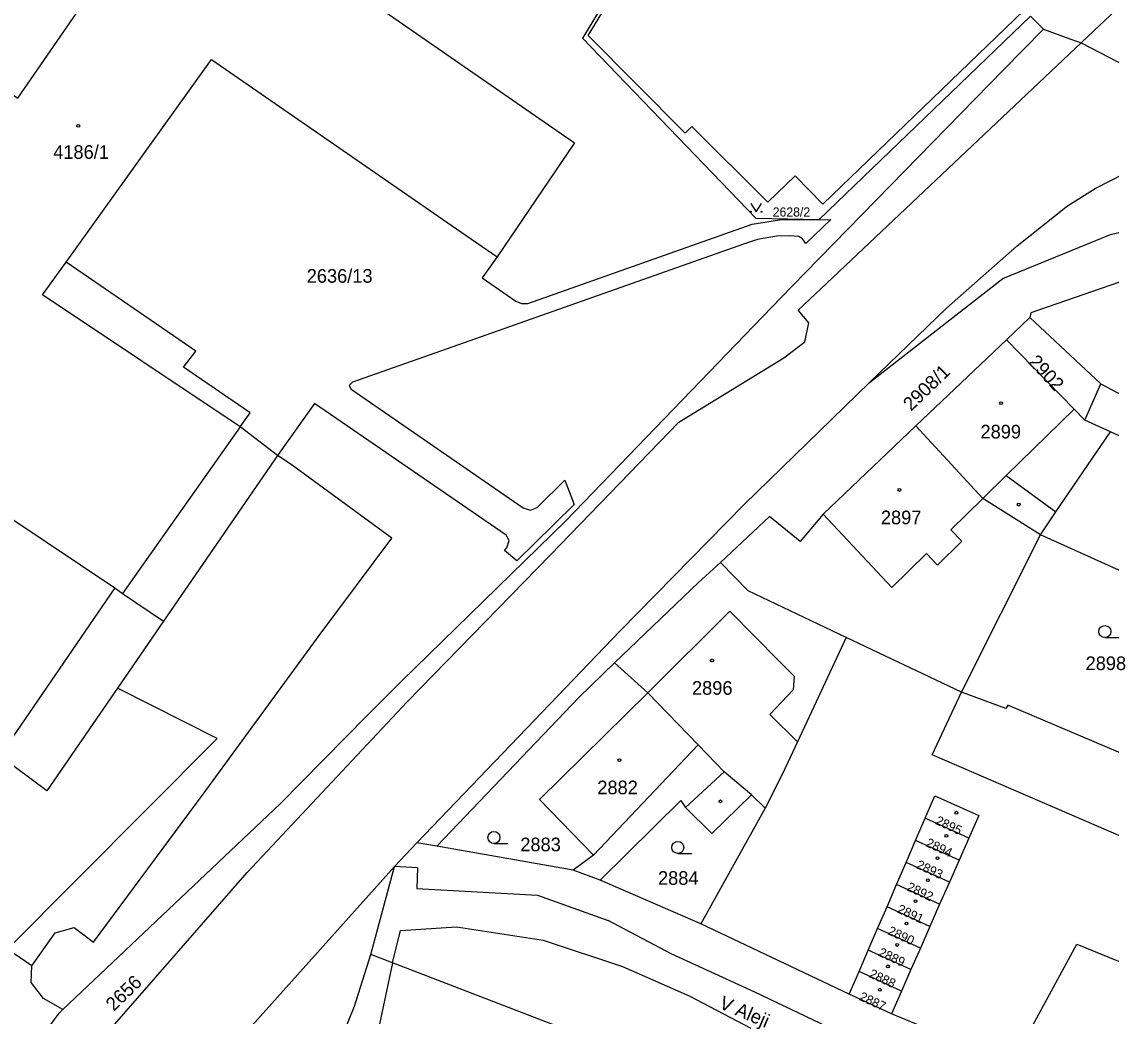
# Model space of a CAD drawing. Extents: x -527335 to -526256, y -1079142 to -1077809.
# Drawn here: x -527027.3 to -526891.4, y -1078723.7 to -1078599.7 of the extents above; entities that cross this region are included whole.
import ezdxf

# ---------------------------------------------------------------- set-up
doc = ezdxf.new("R2010")
doc.units = 0
for name, color, linetype in [('Vrstva 1', 7, 'Continuous'), ('Vrstva 2', 7, 'Continuous'), ('Vrstva 3', 7, 'Continuous'), ('Vrstva 4', 7, 'Continuous'), ('Vrstva 5', 7, 'Continuous'), ('Vrstva 7', 7, 'Continuous')]:
    doc.layers.add(name, color=color, linetype=linetype)

msp = doc.modelspace()

# ---------------------------------------------------------------- linework, layer by layer
at = {"layer": 'Vrstva 1'}
for p, q in [((-526895.17, -1078602.34), (-526879.54, -1078610.46)), ((-526901.58, -1078636.57), (-526904.48, -1078639.35)), ((-526892.72, -1078644.86), (-526901.58, -1078636.57)), ((-526904.48, -1078639.35), (-526915.77, -1078650.08)), ((-526894.69, -1078649.36), (-526892.72, -1078644.86)), ((-527000.1, -1078650.22), (-527014.76, -1078670.99)), ((-526891.48, -1078650.84), (-526894.69, -1078649.36)), ((-526910.1, -1078683.31), (-526900.22, -1078663.69)), ((-526884.81, -1078670.65), (-526900.22, -1078663.69)), ((-526910.1, -1078683.31), (-526924.49, -1078676.46)), ((-526949.23, -1078683.38), (-526953.38, -1078679.65)), ((-526934.57, -1078697.78), (-526936.31, -1078696.09)), ((-526934.57, -1078697.78), (-526942.6, -1078712.19)), ((-526915.81, -1078701.79), (-526914.61, -1078699.02)), ((-526909.18, -1078701.49), (-526914.61, -1078699.02)), ((-526916.99, -1078704.52), (-526915.81, -1078701.79)), ((-526910.4, -1078704.26), (-526915.81, -1078701.79)), ((-526909.18, -1078701.49), (-526910.4, -1078704.26)), ((-526978.03, -1078702.08), (-526980.85, -1078705.02)), ((-526975.57, -1078702.51), (-526978.03, -1078702.08)), ((-526958.56, -1078705.51), (-526975.57, -1078702.51)), ((-526918.19, -1078707.29), (-526916.99, -1078704.52)), ((-526911.6, -1078706.99), (-526916.99, -1078704.52)), ((-526910.4, -1078704.26), (-526911.6, -1078706.99)), ((-526980.85, -1078705.02), (-526998.63, -1078724.92)), ((-526955.16, -1078706.76), (-526958.56, -1078705.51)), ((-526942.6, -1078712.19), (-526955.16, -1078706.76)), ((-526919.38, -1078710.05), (-526918.19, -1078707.29)), ((-526912.82, -1078709.75), (-526918.19, -1078707.29)), ((-526911.6, -1078706.99), (-526912.82, -1078709.75)), ((-526920.56, -1078712.77), (-526919.38, -1078710.05)), ((-526914.03, -1078712.51), (-526919.38, -1078710.05)), ((-526912.82, -1078709.75), (-526914.03, -1078712.51)), ((-526924.11, -1078720.97), (-526942.6, -1078712.19)), ((-526921.72, -1078715.45), (-526920.56, -1078712.77)), ((-526915.22, -1078715.23), (-526920.56, -1078712.77)), ((-526914.03, -1078712.51), (-526915.22, -1078715.23)), ((-526922.88, -1078718.12), (-526921.72, -1078715.45)), ((-526916.4, -1078717.9), (-526921.72, -1078715.45)), ((-526915.22, -1078715.23), (-526916.4, -1078717.9)), ((-526924.11, -1078720.97), (-526922.88, -1078718.12)), ((-526917.58, -1078720.58), (-526922.88, -1078718.12)), ((-526916.4, -1078717.9), (-526917.58, -1078720.58)), ((-526918.83, -1078723.42), (-526924.11, -1078720.97)), ((-526917.58, -1078720.58), (-526918.83, -1078723.42))]:
    msp.add_line(p, q, dxfattribs=at)
for points in [[(-527032.9, -1078614.69), (-527028.96, -1078608.95), (-527028.74, -1078608.62), (-527027.84, -1078609.21), (-527013.93, -1078589.06), (-527018.97, -1078585.47), (-527022.71, -1078582.8), (-527034.32, -1078599.25), (-527035, -1078600.21), (-527045.31, -1078592.89), (-527044.64, -1078591.95), (-527045.34, -1078591.68), (-527030.72, -1078570.54), (-527019.5, -1078578.37), (-527020.66, -1078580.03), (-527011.71, -1078586.28), (-527007.77, -1078580.59), (-526958.39, -1078614.81), (-526968.02, -1078629.02)], [(-526886.71, -1078584.76), (-526887.47, -1078583.94), (-526927.4, -1078622.44), (-526930.86, -1078618.91), (-526934.27, -1078622.19), (-526943.73, -1078612.76), (-526944.56, -1078613.6), (-526956.67, -1078601.43), (-526954.52, -1078597.86), (-526954.82, -1078597.51)], [(-526895.17, -1078602.34), (-526893.54, -1078600.8), (-526885.48, -1078593.16)], [(-526954.82, -1078597.51), (-526957.37, -1078601.73), (-526935.75, -1078624.2), (-526927.86, -1078624.35), (-526901.5, -1078599), (-526901.11, -1078599.39)], [(-526901.11, -1078599.39), (-526900.32, -1078600.17), (-526899.88, -1078600.6)], [(-527022.2, -1078722.85), (-526995.09, -1078697.22), (-526984.19, -1078686.17), (-526979.99, -1078681.95), (-526959.44, -1078661.92), (-526932.63, -1078634.11), (-526929.59, -1078631.02), (-526904.86, -1078605.7), (-526899.88, -1078600.6)], [(-526899.88, -1078600.6), (-526897.02, -1078601.66), (-526895.17, -1078602.34)], [(-527072.22, -1078805.43), (-527063.35, -1078791.03), (-527051.39, -1078772.86), (-527021.8, -1078732.24), (-527016.31, -1078725.38), (-526999.22, -1078705.77), (-526979.26, -1078684.5), (-526961.36, -1078666.17), (-526945.34, -1078649.61), (-526932.24, -1078641.62), (-526929.63, -1078639.61), (-526929.14, -1078637.23), (-526930.46, -1078635.68), (-526927.65, -1078633), (-526895.17, -1078602.34)], [(-527000.1, -1078650.22), (-527024.76, -1078633.76), (-527021.82, -1078629.67), (-527003.67, -1078604.4), (-526973.08, -1078625.53), (-526968.02, -1078629.02)], [(-526921.59, -1078644.68), (-526911.97, -1078635.42), (-526903.16, -1078627.64), (-526896.85, -1078622.64), (-526893.43, -1078620.48), (-526889.76, -1078618.63), (-526885.07, -1078616.68), (-526879.09, -1078614.67), (-526871.32, -1078612.59), (-526869.37, -1078612.14)], [(-526921.59, -1078644.68), (-526904.95, -1078631.71), (-526891.51, -1078626.22), (-526880.24, -1078623.51), (-526871.73, -1078622.35), (-526857.21, -1078622.49), (-526853.17, -1078623.18)], [(-526968.02, -1078629.02), (-526969.91, -1078631.61), (-526965.71, -1078634.53), (-526965, -1078634.84), (-526964.22, -1078634.81), (-526936.22, -1078624.93), (-526932.79, -1078624.4), (-526926.41, -1078624.36), (-526929.51, -1078627.35), (-526929.91, -1078626.76), (-526930.39, -1078626.49), (-526931.57, -1078626.38), (-526933.16, -1078626.45), (-526935.56, -1078626.83), (-526937.3, -1078627.43), (-526974.99, -1078640.74), (-526986.08, -1078644.63), (-526986.49, -1078645.05), (-526986.23, -1078645.53), (-526964.78, -1078660.29), (-526963.85, -1078660.61), (-526963.02, -1078660.27), (-526959.57, -1078656.88), (-526958.42, -1078659.89), (-526960.97, -1078662.37), (-526965.58, -1078666.91), (-526967.12, -1078665.64), (-526966.8, -1078665.3), (-526966.51, -1078664.38), (-526966.91, -1078663.73), (-526990.82, -1078647.32), (-526995.44, -1078653.79), (-527000.1, -1078650.22)], [(-526878.81, -1078628.66), (-526882.67, -1078629.51), (-526901.46, -1078636.01), (-526901.58, -1078636.57)], [(-526894.69, -1078649.36), (-526896.02, -1078648), (-526904.48, -1078639.35)], [(-526978.03, -1078702.08), (-526952.67, -1078675.63), (-526937.2, -1078659.88), (-526921.59, -1078644.68)], [(-526892.72, -1078644.86), (-526888.78, -1078646.91), (-526881.81, -1078650.35)], [(-526915.77, -1078650.08), (-526927.35, -1078661.1), (-526930.24, -1078664.51), (-526934.06, -1078661.4), (-526940.18, -1078667.13)], [(-526900.22, -1078663.69), (-526907.42, -1078659.13), (-526915.77, -1078650.08)], [(-526900.22, -1078663.69), (-526898.33, -1078660.82), (-526891.48, -1078650.84)], [(-526884.81, -1078670.65), (-526875.97, -1078658.01), (-526891.48, -1078650.84)], [(-527028.7, -1078661.6), (-527015.73, -1078670.3), (-527014.76, -1078670.99)], [(-526940.18, -1078667.13), (-526942.9, -1078669.62), (-526953.38, -1078679.65)], [(-526924.49, -1078676.46), (-526936.71, -1078670.65), (-526940.18, -1078667.13)], [(-527014.76, -1078670.99), (-527009.64, -1078674.44), (-527015.39, -1078682.81)], [(-526924.49, -1078676.46), (-526930.54, -1078689.49), (-526931.74, -1078692.06), (-526932.57, -1078693.74), (-526934.57, -1078697.78)], [(-526953.38, -1078679.65), (-526957.82, -1078683.96), (-526975.57, -1078702.51)], [(-527015.39, -1078682.81), (-527024.2, -1078695.62), (-527030.14, -1078691.25), (-527037.08, -1078701.34), (-527042.08, -1078697.91)], [(-527022.2, -1078722.85), (-527024.62, -1078721.48), (-527026.17, -1078719.51), (-527026.1, -1078717.42), (-527029.13, -1078715.35), (-527002.95, -1078689.07), (-527015.39, -1078682.81)], [(-526949.23, -1078683.38), (-526962.73, -1078696.68), (-526956.02, -1078703.63), (-526958.56, -1078705.51)], [(-526936.31, -1078696.09), (-526939.72, -1078693.23), (-526942.93, -1078689.86), (-526949.23, -1078683.38)], [(-526887.47, -1078692.06), (-526904.29, -1078684.93), (-526904.54, -1078685.32), (-526910.1, -1078683.31)], [(-526955.16, -1078706.76), (-526945.11, -1078696.79), (-526944.54, -1078697.69), (-526941.25, -1078700.91), (-526936.31, -1078696.09)], [(-526914.61, -1078699.02), (-526913.4, -1078696.22), (-526907.94, -1078698.67), (-526909.18, -1078701.49)], [(-526943.47, -1078731.53), (-526981.07, -1078717.06), (-526983.77, -1078716), (-526980.85, -1078705.02)], [(-526903.84, -1078729.73), (-526895.72, -1078714.74), (-526874.21, -1078723.48)], [(-527026.84, -1078728.96), (-527025.8, -1078727.55), (-527022.69, -1078723.31), (-527022.2, -1078722.85)], [(-526903.84, -1078729.73), (-526908.52, -1078727.66), (-526909.18, -1078727.41), (-526918.83, -1078723.42)]]:
    msp.add_lwpolyline(points, dxfattribs=at)
at = {"layer": 'Vrstva 3'}
for p, q in [((-526892.21, -1078676.49), (-526890.46, -1078676.49)), ((-526968.43, -1078702.17), (-526966.68, -1078702.17)), ((-526945.49, -1078703.41), (-526943.74, -1078703.41))]:
    msp.add_line(p, q, dxfattribs=at)
msp.add_lwpolyline([(-526936.39, -1078622.38), (-526935.72, -1078623.39), (-526935.05, -1078622.38)], dxfattribs=at)
for centre, radius in [((-526936.39, -1078623.39), 0.067), ((-526935.05, -1078623.39), 0.067), ((-526892.21, -1078675.74), 0.75), ((-526968.43, -1078701.42), 0.75), ((-526945.49, -1078702.66), 0.75)]:
    msp.add_circle(centre, radius, dxfattribs=at)
at = {"layer": 'Vrstva 4'}
for p, q in [((-527005.61, -1078640.76), (-527021.82, -1078629.67)), ((-527007.15, -1078642.76), (-527005.61, -1078640.76)), ((-526998.84, -1078648.48), (-527007.15, -1078642.76)), ((-527000.1, -1078650.22), (-526998.84, -1078648.48)), ((-526904.5, -1078656.28), (-526896.02, -1078648)), ((-526995.44, -1078653.79), (-527009.64, -1078674.44)), ((-526993.74, -1078654.92), (-526995.44, -1078653.79)), ((-526981.15, -1078664.11), (-526993.74, -1078654.92)), ((-526907.42, -1078659.13), (-526904.5, -1078656.28)), ((-526904.5, -1078656.28), (-526898.33, -1078660.82)), ((-526911.43, -1078663.04), (-526907.42, -1078659.13)), ((-526927.35, -1078661.1), (-526918.8, -1078670.23)), ((-526910.03, -1078664.47), (-526911.43, -1078663.04)), ((-526990.1, -1078676.05), (-526981.15, -1078664.11)), ((-526913.07, -1078667.44), (-526910.03, -1078664.47)), ((-526918.8, -1078670.23), (-526914.47, -1078666)), ((-526914.47, -1078666), (-526913.07, -1078667.44)), ((-527015.73, -1078670.3), (-527030.14, -1078691.25)), ((-526949.23, -1078683.38), (-526939, -1078673.18)), ((-526939, -1078673.18), (-526932.89, -1078679.41)), ((-527004.71, -1078696.01), (-526990.1, -1078676.05)), ((-526932.89, -1078679.41), (-526930.97, -1078681.31)), ((-526930.97, -1078681.31), (-526931.09, -1078683.01)), ((-526931.09, -1078683.01), (-526934, -1078686.1)), ((-526913.74, -1078691.1), (-526910.1, -1078683.31)), ((-526934, -1078686.1), (-526930.54, -1078689.49)), ((-526956.02, -1078703.63), (-526942.93, -1078689.86)), ((-526884.03, -1078703.98), (-526913.74, -1078691.1)), ((-526944.54, -1078697.69), (-526939.72, -1078693.23)), ((-527018.38, -1078714.47), (-527004.71, -1078696.01)), ((-526977.98, -1078705.21), (-526980.85, -1078705.02)), ((-526977.98, -1078705.21), (-526978.05, -1078707.78)), ((-526978.05, -1078707.78), (-526962.99, -1078708.6)), ((-526962.99, -1078708.6), (-526954.18, -1078711.78)), ((-527023.18, -1078713.29), (-527020.8, -1078712.65)), ((-527020.8, -1078712.65), (-527018.38, -1078714.47)), ((-526980.09, -1078713), (-526973.08, -1078712.58)), ((-526973.08, -1078712.58), (-526962.3, -1078714.24)), ((-526946.33, -1078715.93), (-526954.18, -1078711.78)), ((-527026.1, -1078717.42), (-527023.18, -1078713.29)), ((-526981.07, -1078717.06), (-526980.09, -1078713)), ((-526962.3, -1078714.24), (-526952.38, -1078717.51)), ((-526985.84, -1078722.46), (-526983.77, -1078716)), ((-526935.89, -1078720.7), (-526946.33, -1078715.93)), ((-526981.07, -1078717.06), (-526982.85, -1078725.3)), ((-526952.38, -1078717.51), (-526944.09, -1078721.15)), ((-526925.87, -1078725.49), (-526935.89, -1078720.7)), ((-526944.09, -1078721.15), (-526936.39, -1078725.2)), ((-526987.91, -1078727.56), (-526985.84, -1078722.46))]:
    msp.add_line(p, q, dxfattribs=at)
at = {"layer": 'Vrstva 5'}
for centre in [(-527020.29, -1078612.68), (-526905.16, -1078647.26), (-526917.84, -1078658.08), (-526902.95, -1078659.91), (-526941.22, -1078679.35), (-526952.78, -1078691.78), (-526940.18, -1078696.91), (-526910.73, -1078698.33), (-526911.98, -1078701.22), (-526913.09, -1078703.99), (-526914.3, -1078706.75), (-526915.82, -1078709.35), (-526916.95, -1078712.14), (-526918.11, -1078714.82), (-526919.27, -1078717.49), (-526920.29, -1078720.4)]:
    msp.add_circle(centre, 0.175, dxfattribs=at)

# ---------------------------------------------------------------- texts
at = {"layer": 'Vrstva 2'}
for s, height, p in [('4186/1', 1.7, (-527023.42, -1078616.79)), ('2628/2', 1.14, (-526933.64, -1078623.99)), ('2636/13', 1.7, (-526991.79, -1078632.24)), ('2899', 1.7, (-526907.72, -1078651.66)), ('2897', 1.7, (-526920.15, -1078662.36)), ('2898', 1.7, (-526894.61, -1078680.54)), ('2896', 1.7, (-526943.72, -1078683.62)), ('2882', 1.7, (-526955.53, -1078696.03)), ('2883', 1.7, (-526965.14, -1078703.14)), ('2884', 1.7, (-526947.96, -1078707.32))]:
    msp.add_text(s, height=height, dxfattribs=at).set_placement(p)
for s, height, rotation, p in [('2902', 1.7, 313, (-526901.84, -1078642.2)), ('2908/1', 1.7, 44, (-526916.38, -1078648.33)), ('2895', 1.14, 335, (-526913.44, -1078699.7)), ('2894', 1.14, 335, (-526914.64, -1078702.47)), ('2893', 1.14, 335, (-526915.82, -1078705.2)), ('2892', 1.14, 335, (-526917.02, -1078707.97)), ('2891', 1.14, 335, (-526918.21, -1078710.73)), ('2890', 1.14, 335, (-526919.39, -1078713.45)), ('2889', 1.14, 335, (-526920.55, -1078716.13)), ('2888', 1.14, 335, (-526921.71, -1078718.8)), ('2656', 1.7, 44, (-527015.86, -1078723.17)), ('2887', 1.14, 335, (-526922.94, -1078721.65))]:
    msp.add_text(s, height=height, rotation=rotation, dxfattribs=at).set_placement(p)
at = {"layer": 'Vrstva 7'}
msp.add_text('V Aleji', height=1.7, rotation=337, dxfattribs=at).set_placement((-526940.44, -1078722.67))

doc.saveas('drawing.dxf')
